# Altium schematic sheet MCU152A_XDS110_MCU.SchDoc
size 431 x 279 mm; Date: Not shown in title block; ApprovedBy: Not shown in title block; CheckedBy: Not shown in title block; Author: Not shown in title block; CompanyName: Not shown in title block; Engineer: Not shown in title block; Organization: Not shown in title block; Address1: Not shown in title block; Address2: Not shown in title block; Address3: Not shown in title block; Address4: Not shown in title block; DocumentNumber: 7; Revision: Use project parameter SCH_Rev; SheetNumber: 7; SheetTotal: 8; PageSetup: Record=PageOptions¦CenterHorizontal=True¦CenterVertical=True¦PrintScale=1.00¦XCorrection=1.00¦YCorrection=1.00¦PrintKind=0¦BorderSize=5000000¦LeftOffset=0¦BottomOffset=0¦Orientation=2¦PaperLength=1000¦PaperWidth=1000¦Scale=100¦PaperSource=15¦PrintQuality=600¦MediaType=1¦DitherType=10¦PaperKind=Letter¦PrintScaleMode=1
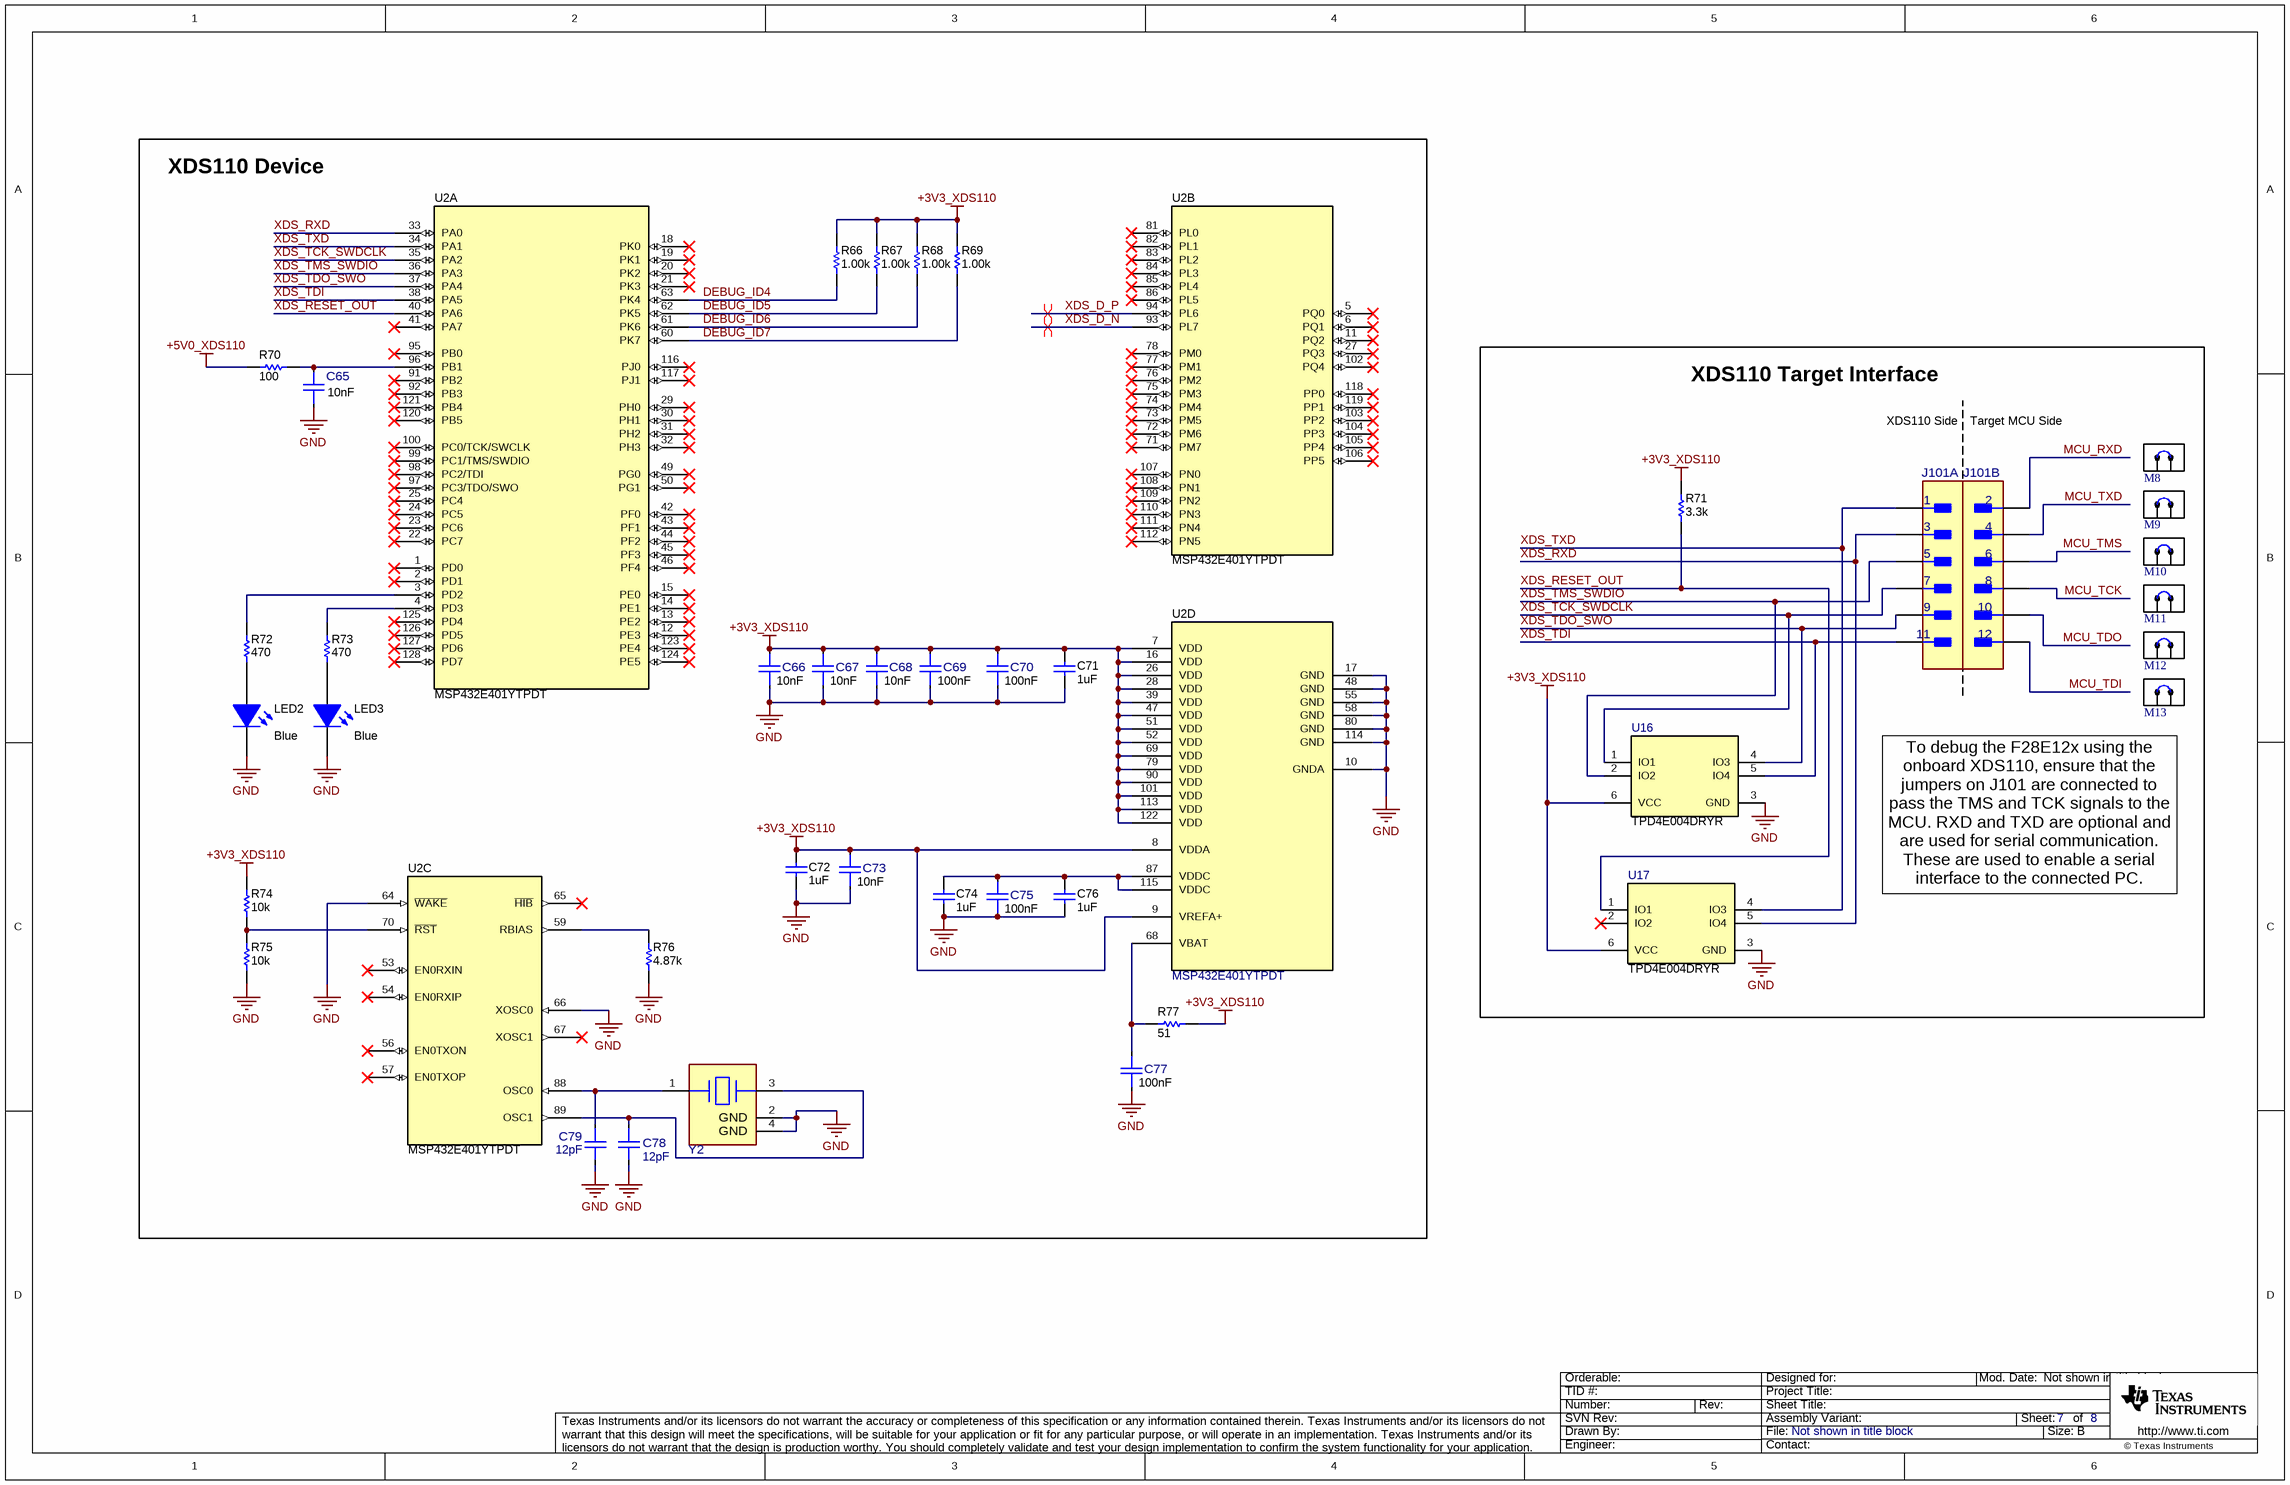
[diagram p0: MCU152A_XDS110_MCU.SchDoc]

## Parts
C65  Cap_F: 10nF  [FP-885012205050_0402-MFG]  (hidden comment: 885012205050)
C66  Cap_F: 10nF  [FP-885012205050_0402-MFG]  (hidden comment: 885012205050)
C67  Cap_F: 10nF  [FP-885012205050_0402-MFG]  (hidden comment: 885012205050)
C68  Cap_F: 10nF  [FP-885012205050_0402-MFG]  (hidden comment: 885012205050)
C69  Cap_F: 100nF  [FP-885012205018_0402-MFG]  (hidden comment: 885012205018)
C70  Cap_F: 100nF  [FP-885012205018_0402-MFG]  (hidden comment: 885012205018)
C71  ValueDisplayed: 1uF  [0402]  (hidden comment: 885012105012)
C72  ValueDisplayed: 1uF  [0402]  (hidden comment: 885012105012)
C73  Cap_F: 10nF  [FP-885012205050_0402-MFG]  (hidden comment: 885012205050)
C74  ValueDisplayed: 1uF  [0402]  (hidden comment: 885012105012)
C75  Cap_F: 100nF  [FP-885012205018_0402-MFG]  (hidden comment: 885012205018)
C76  ValueDisplayed: 1uF  [0402]  (hidden comment: 885012105012)
C77  Cap_F: 100nF  [FP-885012205018_0402-MFG]  (hidden comment: 885012205018)
C78  ValueDisplayed: 12pF  [FP-885392005127_0402-MFG]  (hidden comment: 885392005127)
C79  ValueDisplayed: 12pF  [FP-885392005127_0402-MFG]  (hidden comment: 885392005127)
J101  61301221121  [FP-61301221121_HDR12-MFG]  (value not drawn)  (parts A,B of 2)
LED2  value Blue  [WL-SMCW_Blue_0805]  (hidden comment: 150080BS75000)
LED3  value Blue  [WL-SMCW_Blue_0805]  (hidden comment: 150080BS75000)
M8  60900213421  [Wurth_60900213421]  (value not drawn)
M9  60900213421  [Wurth_60900213421]  (value not drawn)
M10  60900213421  [Wurth_60900213421]  (value not drawn)
M11  60900213421  [Wurth_60900213421]  (value not drawn)
M12  60900213421  [Wurth_60900213421]  (value not drawn)
M13  60900213421  [Wurth_60900213421]  (value not drawn)
R66  ValueDisplayed: 1.00k  [0402]  (hidden comment: CRCW04021K00FKED)
R67  ValueDisplayed: 1.00k  [0402]  (hidden comment: CRCW04021K00FKED)
R68  ValueDisplayed: 1.00k  [0402]  (hidden comment: CRCW04021K00FKED)
R69  ValueDisplayed: 1.00k  [0402]  (hidden comment: CRCW04021K00FKED)
R70  ValueDisplayed: 100  [0402]  (hidden comment: CRCW0402100RJNED)
R71  ValueDisplayed: 3.3k  [0402]  (hidden comment: CRCW04023K30JNED)
R72  ValueDisplayed: 470  [0402]  (hidden comment: RC0402FR-07470RL)
R73  ValueDisplayed: 470  [0402]  (hidden comment: RC0402FR-07470RL)
R74  ValueDisplayed: 10k  [0402]  (hidden comment: CRCW040210K0JNED)
R75  ValueDisplayed: 10k  [0402]  (hidden comment: CRCW040210K0JNED)
R76  ValueDisplayed: 4.87k  [0402]  (hidden comment: CRCW04024K87FKED)
R77  ValueDisplayed: 51  [0402]  (hidden comment: CRCW040251R0JNED)
U2  MSP432E401YTPDT  [PDT0128A]  (parts A,B,C,D of 4)
U16  TPD4E004DRYR  [DRY0006A]
U17  TPD4E004DRYR  [DRY0006A]
Y2  830064296  [FP-830064296_SMT4_3MM4_2MM7-MFG]  (value not drawn)

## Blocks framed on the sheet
XDS110 Device: C65-C79 LED2 LED3 R66-R70 R72-R77 U2 Y2
XDS110 Target Interface: J101 M8-M13 R71 U16 U17

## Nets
+3V3_XDS110: C66.2 C67.2 C68.2 C69.2 C70.2 C71.1 C72.1 C73.2 R66.2 R67.2 R68.2 R69.2 R71.2 R74.2 R77.2 U2.7(VDD) U2.8(VDDA) U2.9(VREFA+) U2.16(VDD) U2.26(VDD) U2.28(VDD) U2.39(VDD) U2.47(VDD) U2.51(VDD) U2.52(VDD) U2.69(VDD) U2.79(VDD) U2.90(VDD) U2.101(VDD) U2.113(VDD) U2.122(VDD) U16.6(VCC) U17.6(VCC)
+5V0_XDS110: R70.1
GND: C65.1 C66.1 C67.1 C68.1 C69.1 C70.1 C71.2 C72.2 C73.1 C74.2 C75.1 C76.2 C77.1 C78.2 C79.2 LED2.1(K) LED3.1(K) R75.1 R76.1 U2.10(GNDA) U2.17(GND) U2.48(GND) U2.55(GND) U2.58(GND) U2.64(~{WAKE}) U2.66(XOSC0) U2.80(GND) U2.114(GND) U16.3(GND) U17.3(GND) Y2.2(GND) Y2.4(GND)
DEBUG_ID4: R66.1 U2.63(PK4)
DEBUG_ID5: R67.1 U2.62(PK5)
DEBUG_ID6: R68.1 U2.61(PK6)
DEBUG_ID7: R69.1 U2.60(PK7)
MCU_RXD: J101.2
MCU_TCK: J101.8
MCU_TDI: J101.12
MCU_TDO: J101.10
MCU_TMS: J101.6
MCU_TXD: J101.4
XDS_D_N: U2.93(PL7)
XDS_D_P: U2.94(PL6)
XDS_RESET_OUT: R71.1 U2.40(PA6) U17.1(IO1)
XDS_RXD: J101.3 U2.33(PA0) U17.5(IO4)
XDS_TCK_SWDCLK: J101.7 U2.35(PA2) U16.1(IO1)
XDS_TDI: J101.11 U2.38(PA5) U16.5(IO4)
XDS_TDO_SWO: J101.9 U2.37(PA4) U16.4(IO3)
XDS_TMS_SWDIO: J101.5 U2.36(PA3) U16.2(IO2)
XDS_TXD: J101.1 U2.34(PA1) U17.4(IO3)
NetC65_2: C65.2 R70.2 U2.96(PB1)
NetC74_1: C74.1 C75.2 C76.1 U2.87(VDDC) U2.115(VDDC)
NetC77_2: C77.2 R77.1 U2.68(VBAT)
NetC78_1: C78.1 U2.89(OSC1) Y2.3(2_Crystal)
NetC79_1: C79.1 U2.88(OSC0) Y2.1(1_Crystal)
NetLED2_2: LED2.2(A) R72.1
NetLED3_2: LED3.2(A) R73.1
NetR72_2: R72.2 U2.3(PD2)
NetR73_2: R73.2 U2.4(PD3)
NetR74_1: R74.1 R75.2 U2.70(~{RST})
NetR76_2: R76.2 U2.59(RBIAS)

Not connected (* = marked no-connect by the designer): U2 1(PD0)* 2(PD1)* 5(PQ0)* 6(PQ1)* 11(PQ2)* 12(PE3)* 13(PE2)* 14(PE1)* 15(PE0)* 18(PK0)* 19(PK1)* 20(PK2)* 21(PK3)* 22(PC7)* 23(PC6)* 24(PC5)* 25(PC4)* 27(PQ3)* 29(PH0)* 30(PH1)* 31(PH2)* 32(PH3)* 41(PA7)* 42(PF0)* 43(PF1)* 44(PF2)* 45(PF3)* 46(PF4)* 49(PG0)* 50(PG1)* 53(EN0RXIN)* 54(EN0RXIP)* 56(EN0TXON)* 57(EN0TXOP)* 65(~{HIB})* 67(XOSC1)* 71(PM7)* 72(PM6)* 73(PM5)* 74(PM4)* 75(PM3)* 76(PM2)* 77(PM1)* 78(PM0)* 81(PL0)* 82(PL1)* 83(PL2)* 84(PL3)* 85(PL4)* 86(PL5)* 91(PB2)* 92(PB3)* 95(PB0)* 97(PC3/TDO/SWO)* 98(PC2/TDI)* 99(PC1/TMS/SWDIO)* 100(PC0/TCK/SWCLK)* 102(PQ4)* 103(PP2)* 104(PP3)* 105(PP4)* 106(PP5)* 107(PN0)* 108(PN1)* 109(PN2)* 110(PN3)* 111(PN4)* 112(PN5)* 116(PJ0)* 117(PJ1)* 118(PP0)* 119(PP1)* 120(PB5)* 121(PB4)* 123(PE4)* 124(PE5)* 125(PD4)* 126(PD5)* 127(PD6)* 128(PD7)*; U17 2(IO2)*

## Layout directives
differential pair: XDS_D_N, XDS_D_P

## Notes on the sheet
- XDS110 Side
- Target MCU Side
- (near M13) To debug the F28E12x using the onboard XDS110, ensure that the jumpers on J101 are connected to pass the TMS and TCK signals to the MCU. RXD and TXD are optional and are used for serial communication. These are used to enable a serial interface to the connected PC.

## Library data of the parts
C65-C68 C73 = CMP-0090363-1: 10000pF ±10% 25V Ceramic Capacitor X7R 0402 (1005 Metric); Manufacturer: Wurth Electronics; SizeZ_mm: 0.55mm; AEC Qualified: No; Value: 10nF; TempCo: 15%
C69 C70 C75 C77 = CMP-0090362-1: 0.1µF ±10% 10V Ceramic Capacitor X7R 0402 (1005 Metric); Manufacturer: Wurth Electronics; AEC Qualified: No; Value: 100nF; SizeZ_mm: 0.55mm; ValueDisplayed: 100000pF; TempCo: 15%
C71 C72 C74 C76 = CMP-0064924-2: CAP, CERM, 1 uF, 10 V,+/- 20%, X5R, 0402; Manufacturer: Wurth Elektronik; Polarized: N; Value: 1uF; U/M: EA; Cap_F: 1µF; Value1: Unknown; VDC_V: 10V; TaMin_C: -55°C; TaMax_C: 85°C; SizeArea_mm2: 0.5; SizeAreaWB_mm2: 3; SizeX_mm: 1; SizeZ_mm: 0.6; AEC Category: Q200
C78 C79 = CMP-0124909-1: 12 pF ±2% 50V Ceramic Capacitor C0G, NP0 0402 (1005 Metric); Manufacturer: Wurth; AEC Qualified: No; SizeZ_mm: 0.55mm; TempCo: 30ppm/°C; Value: 12pF
J101 = CMP-0092423-1: THT Vertical Pin Header WR-PHD, Pitch 2.54 mm, Dual Row, 12 pins; Manufacturer: Wurth Electronics; Is Female: no; DUT-Pitch_mm: 2.54mm; Row_Count: 2; Current_A: 3A; Voltage_V: 250V; Conn Gender: Male; Conn Orientation: Straight; SizeZ_mm: 8.89mm; ContactFinish: Gold
LED2 LED3 = CMP-0002959-3: LED, Blue, SMD; Manufacturer: Wurth Elektronik; Vf_V: 3.2V; Value1: 0.105W; Angle: 140; Type: InGaN; Power_TotalModule: 105mW; Tjmax_C: 85°C; Vr_V: 5V; Io_A: 20mA
M8-M13 = CMP-0003761-2: Shunt, 2.54mm, Gold, Black; Manufacturer: Wurth Elektronik
R66-R69 = CMP-0026071-3: RES, 1.00 k, 1%, 0.063 W, AEC-Q200 Grade 0, 0402; Manufacturer: Vishay-Dale; Power_W: 63mW; TempCo: 100 ppm/C; Value_Code: 1k00; Value: 1.00k; EIA_Code: E96; Res_ohm: 1k; SizeX_mm: 1; SizeY_mm: 0.5; SizeZ_mm: 0.6; Value2: 0.063W; AEC Qualified: Y; VDC_V: 50V; AEC Category: Q200; AEC Grade: 0
R70 = CMP-0026824-3: RES, 100, 5%, 0.063 W, AEC-Q200 Grade 0, 0402; Manufacturer: Vishay-Dale; Value: 100; Value_Code: 100R; Power_W: 63mW; Value2: 0.063W; VDC_V: 50V; TempCo: 200 ppm/C; SizeArea_mm2: 0.5; SizeX_mm: 1; SizeZ_mm: 0.6; EIA_Code: E24; AEC Category: Q200; AEC Qualified: Y; AEC Grade: 0
R71 = CMP-0026918-5: RES, 3.3 k, 5%, 0.063 W, AEC-Q200 Grade 0, 0402; Manufacturer: Vishay-Dale; Value: 3.3k; Value_Code: 3k30; Power_W: 63mW; Value2: 0.063W; VDC_V: 50V; TempCo: 200 ppm/C; SizeArea_mm2: 0.5; SizeX_mm: 1; SizeZ_mm: 0.6; EIA_Code: E24; AEC Category: Q200; AEC Qualified: Y; AEC Grade: 0
R72 R73 = CMP-0026736-1: RES, 470, 1%, 0.063 W, 0402; Manufacturer: Yageo America; Power_W: 63mW; TempCo: 100 ppm/C; Value_Code: 470R; U/M: EA; Value: 470; SizeX_mm: 1; SizeY_mm: 0.5; SizeZ_mm: 0.6; Value2: 0.063W; AEC Qualified: N; VDC_V: 50V; AEC Category: Q200
R74 R75 = CMP-0026825-5: RES, 10 k, 5%, 0.063 W, AEC-Q200 Grade 0, 0402; Manufacturer: Vishay-Dale; Value: 10k; Value_Code: 10k0; Power_W: 63mW; Value2: 0.063W; VDC_V: 50V; TempCo: 200 ppm/C; SizeArea_mm2: 0.5; SizeX_mm: 1; SizeZ_mm: 0.6; EIA_Code: E24; AEC Category: Q200; AEC Qualified: Y; AEC Grade: 0
R76 = CMP-0026413-2: RES, 4.87 k, 1%, 0.063 W, AEC-Q200 Grade 0, 0402; Manufacturer: Vishay-Dale; Value: 4.87k; Value_Code: 4k87; Power_W: 63mW; Value2: 0.063W; VDC_V: 50V; TempCo: 100 ppm/C; SizeArea_mm2: 0.5; SizeX_mm: 1; SizeZ_mm: 0.6; EIA_Code: E96; AEC Category: Q200; AEC Qualified: Y; AEC Grade: 0
R77 = CMP-0026946-3: RES, 51, 5%, 0.063 W, AEC-Q200 Grade 0, 0402; Manufacturer: Vishay-Dale; Value: 51; Value_Code: 51R0; Power_W: 63mW; Value2: 0.063W; VDC_V: 50V; TempCo: 200 ppm/C; SizeArea_mm2: 0.5; SizeX_mm: 1; SizeZ_mm: 0.6; EIA_Code: E24; AEC Category: Q200; AEC Qualified: Y; AEC Grade: 0
U2 = CMP-0077953-1: MSP432E401YTPDT, PDT0128A (TQFP-128); Alternate PartNumber: MSP432E401YTPDTR; Alternate Manufacturer: Texas Instruments; SizeAreaWB_mm2: 324; SizeZ_mm: 1.2; SizeX_mm: 16; SizeArea_mm2: 256; CompType: IC; AEC Qualified: N; AEC Category: Q200
U16 U17 = CMP-0043115-3: 4-Channel ESD Protection Array for High-Speed Data Interfaces, DRY0006A (USON-6); Manufacturer: Texas Instruments; IO Leakage Current(nA): 1; USB High Speed: TRUE; IO Capacitance(Typ)(pF): 1.6; Eco-Plan: Green (RoHS & no Sb/Br); IEC 61000-4-2 Contact(+/- kV): 8; Breakdown Voltage(Min)(V): 6; IEC 61000-4-2 Air-Gap(+/- kV): 12; AEC Category: Q200; AEC Qualified: N; CompType: IC; SizeAreaWB_mm2: 4.9; SizeArea_mm2: 1.45; SizeX_mm: 1.0; SizeZ_mm: 0.6; Rating: Catalog
Y2 = CMP-0094478-1: Crystal 16 MHz ±20ppm Crystal 8pF 70 Ohms 4-SMD, No Lead; Manufacturer: Wurth; SizeZ_mm: 0.8mm; Frequency_Fixed: 16MHz; Esr: 70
